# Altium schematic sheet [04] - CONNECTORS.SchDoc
size A4; DocumentNumber: 4; SheetNumber: 4; SheetTotal: 5
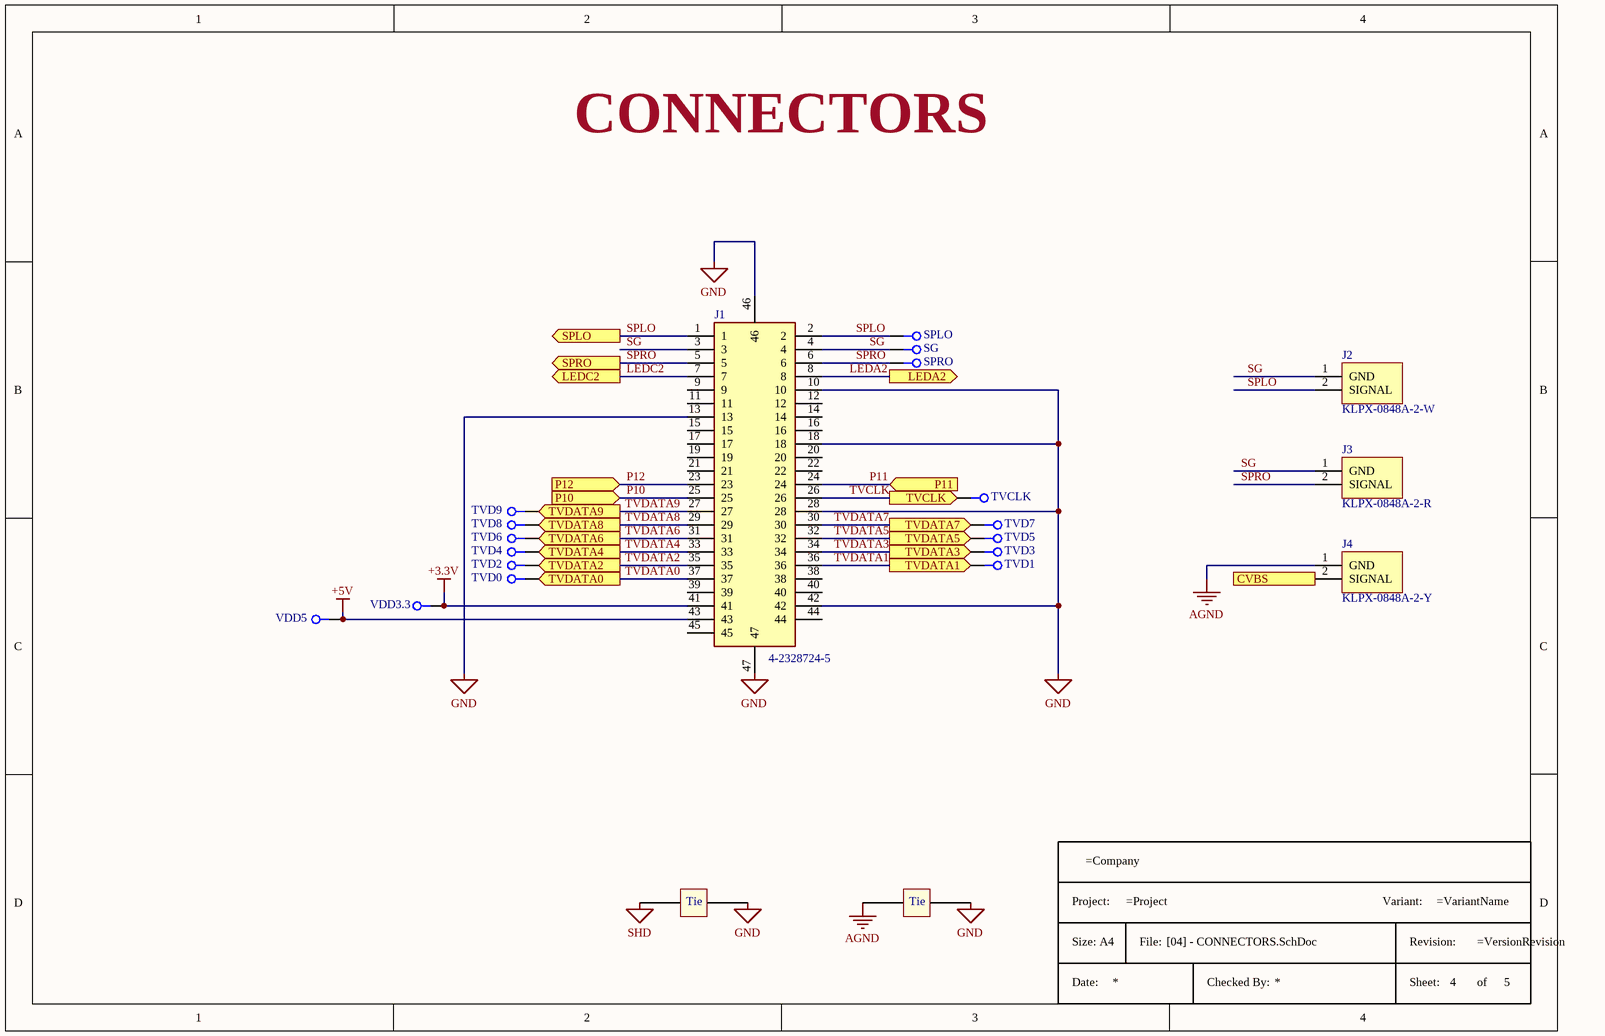
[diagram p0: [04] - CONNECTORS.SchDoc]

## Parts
*  Title Block A4  (value not drawn)  (graphical)
J1  4-2328724-5  [423287245]
J2  KLPX-0848A-2-W  [KLPX0848A2W]
J3  KLPX-0848A-2-R  [KLPX0848A2R]
J4  KLPX-0848A-2-Y  [KLPX0848A2Y]
SG  TP_25MILC  [TP_25C]  (value not drawn)  (no BOM)
SPLO  TP_25MILC  [TP_25C]  (value not drawn)  (no BOM)
SPRO  TP_25MILC  [TP_25C]  (value not drawn)  (no BOM)
T1  NET TIE  [NET_TIE]  (value not drawn)  (net tie, no BOM)
T2  NET TIE  [NET_TIE]  (value not drawn)  (net tie, no BOM)
TVCLK  TP_25MILC  [TP_25C]  (value not drawn)  (no BOM)
TVD0  TP_25MILC  [TP_25C]  (value not drawn)  (no BOM)
TVD1  TP_25MILC  [TP_25C]  (value not drawn)  (no BOM)
TVD2  TP_25MILC  [TP_25C]  (value not drawn)  (no BOM)
TVD3  TP_25MILC  [TP_25C]  (value not drawn)  (no BOM)
TVD4  TP_25MILC  [TP_25C]  (value not drawn)  (no BOM)
TVD5  TP_25MILC  [TP_25C]  (value not drawn)  (no BOM)
TVD6  TP_25MILC  [TP_25C]  (value not drawn)  (no BOM)
TVD7  TP_25MILC  [TP_25C]  (value not drawn)  (no BOM)
TVD8  TP_25MILC  [TP_25C]  (value not drawn)  (no BOM)
TVD9  TP_25MILC  [TP_25C]  (value not drawn)  (no BOM)
VDD3.3  TP_25MILC  [TP_25C]  (value not drawn)  (no BOM)
VDD5  TP_25MILC  [TP_25C]  (value not drawn)  (no BOM)

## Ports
CVBS (in), LEDA2 (out), LEDC2 (out), P10 (in), P11 (in), P12 (in), SPLO (out), SPRO (out), TVCLK (out), TVDATA0 (out), TVDATA1 (out), TVDATA2 (out), TVDATA3 (out), TVDATA4 (out), TVDATA5 (out), TVDATA6 (out), TVDATA7 (out), TVDATA8 (out), TVDATA9 (out)

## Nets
+3.3V: J1.41 VDD3.3.1
+5V: J1.43 VDD5.1
AGND: J4.1(GND) T1.1
GND: J1.10 J1.13 J1.18 J1.28 J1.42 J1.46 J1.47 T1.2 T2.2
SHD: T2.1
CVBS: J4.2(SIGNAL) ; port CVBS
LEDA2: J1.8 ; port LEDA2
LEDC2: J1.7 ; port LEDC2
P10: J1.25 ; port P10
P11: J1.24 ; port P11
P12: J1.23 ; port P12
SG: J1.3 J1.4 J2.1(GND) J3.1(GND) SG.1
SPLO: J1.1 J1.2 J2.2(SIGNAL) SPLO.1 ; port SPLO
SPRO: J1.5 J1.6 J3.2(SIGNAL) SPRO.1 ; port SPRO
TVCLK: J1.26 TVCLK.1 ; port TVCLK
TVDATA0: J1.37 TVD0.1 ; port TVDATA0
TVDATA1: J1.36 TVD1.1 ; port TVDATA1
TVDATA2: J1.35 TVD2.1 ; port TVDATA2
TVDATA3: J1.34 TVD3.1 ; port TVDATA3
TVDATA4: J1.33 TVD4.1 ; port TVDATA4
TVDATA5: J1.32 TVD5.1 ; port TVDATA5
TVDATA6: J1.31 TVD6.1 ; port TVDATA6
TVDATA7: J1.30 TVD7.1 ; port TVDATA7
TVDATA8: J1.29 TVD8.1 ; port TVDATA8
TVDATA9: J1.27 TVD9.1 ; port TVDATA9

Not connected (* = marked no-connect by the designer): J1 9 11 12 14 15 16 17 19 20 21 22 38 39 40 44 45

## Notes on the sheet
- CONNECTORS

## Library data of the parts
J1 = 4-2328724-5: FPC Connector; 0.3mm pitch front flip FPC; 45pos; Manufacturer: TE Connectivity AMP; Actuator Material: Thermoplastic; Number of Positions: 45; Voltage Rating: 30V; Current Rating: 500mA
J2 = KLPX-0848A-2-W: Conn RCA F 2 POS 4.5mm Solder RA Thru-Hole 2 Terminal 1 Port; Manufacturer: Kycon; Number of Ports: 1; Gender: Female; Voltage Rating: 500V; Number of Contacts: 2
J3 = KLPX-0848A-2-R: Conn RCA F 2 POS 4.5mm Solder RA Thru-Hole 2 Terminal 1 Port; Manufacturer: Kycon; Number of Ports: 1; Gender: Female; Voltage Rating: 500V; Number of Contacts: 2
J4 = KLPX-0848A-2-Y: Conn RCA F 2 POS 4.5mm Solder RA Thru-Hole 2 Terminal 1 Port; Manufacturer: Kycon; Number of Ports: 1; Gender: Female; Voltage Rating: 500V; Number of Contacts: 2
SG SPLO SPRO TVCLK TVD0-TVD9 VDD3.3 VDD5 = TP_25MILC: Test Point 25mil
T1 T2 = NET_TIE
